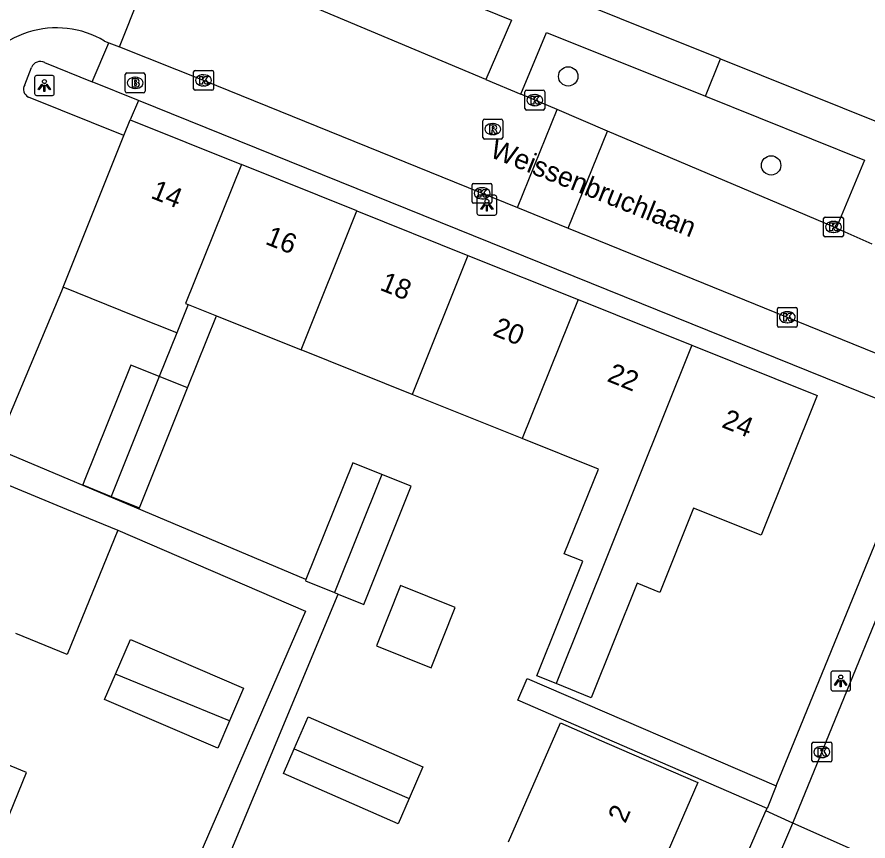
# Model space of a CAD drawing. Extents: x 162812 to 163818, y 381639 to 382470.
# Drawn here: x 163309.93 to 163352.9, y 382068.45 to 382110.03 of the extents above; entities that cross this region are included whole.
import ezdxf

# ---------------------------------------------------------------- set-up
doc = ezdxf.new("R2010")
doc.units = 0
for name, color, linetype in [('IMGEO_Boom', 7, 'Continuous'), ('IMGEO_Brandkraan', 7, 'Continuous'), ('IMGEO_Groenvoorziening', 7, 'Continuous'), ('IMGEO_Kolk', 7, 'Continuous'), ('IMGEO_Lichtpunt', 7, 'Continuous'), ('IMGEO_Openbare_ruimte_label', 7, 'Continuous'), ('IMGEO_Pand', 7, 'Continuous'), ('IMGEO_Pand_nummerreeks', 7, 'Continuous'), ('IMGEO_Parkeervlak_open', 7, 'Continuous'), ('IMGEO_Rijbaan_lokaal_open', 7, 'Continuous'), ('IMGEO_Rioolput', 7, 'Continuous'), ('IMGEO_Voetpad_open', 7, 'Continuous')]:
    doc.layers.add(name, color=color, linetype=linetype)

msp = doc.modelspace()

# ---------------------------------------------------------------- linework, layer by layer
at = {"layer": 'IMGEO_Boom'}
for centre in [(163337.76, 382107.037), (163348.006, 382102.545)]:
    msp.add_circle(centre, 0.489, dxfattribs=at)
at = {"layer": 'IMGEO_Brandkraan'}
for p, q in [((163315.397, 382106.284), (163315.397, 382107.136)), ((163315.472, 382107.21), (163316.324, 382107.21)), ((163316.398, 382107.136), (163316.398, 382106.284)), ((163315.885, 382106.99), (163315.91, 382106.99)), ((163315.908, 382106.43), (163315.883, 382106.43)), ((163316.324, 382106.21), (163315.472, 382106.21))]:
    msp.add_line(p, q, dxfattribs=at)
for points in [[(163315.397, 382106.284), (163315.397, 382107.136)], [(163315.472, 382107.21), (163316.324, 382107.21)], [(163316.398, 382107.136), (163316.398, 382106.284)], [(163315.745, 382106.91), (163315.745, 382106.51), (163315.958, 382106.51)], [(163315.976, 382106.91), (163315.745, 382106.91)], [(163315.924, 382106.829), (163315.87, 382106.829), (163315.87, 382106.753)], [(163315.87, 382106.753), (163315.923, 382106.753)], [(163315.932, 382106.677), (163315.87, 382106.677), (163315.87, 382106.596)], [(163315.87, 382106.596), (163315.932, 382106.596)], [(163316.324, 382106.21), (163315.472, 382106.21)]]:
    msp.add_lwpolyline(points, dxfattribs=at)
for centre, radius, start, end in [((163315.474, 382107.134), 0.0765, 91.552, 178.448), ((163315.474, 382107.134), 0.0765, 91.552, 178.448), ((163316.322, 382107.134), 0.0765, 1.552, 88.448), ((163316.322, 382107.134), 0.0765, 1.552, 88.448), ((163315.925, 382106.791), 0.0379, 267.8285, 90.9355), ((163315.933, 382106.636), 0.0404, 269.8759, 90.5077), ((163315.98, 382106.765), 0.145, 59.4692, 91.5367), ((163316.005, 382106.812), 0.0922, 285.5137, 58.1501), ((163316.01, 382106.62), 0.105, 301.3115, 78.989), ((163315.474, 382106.286), 0.0765, 181.552, 268.448), ((163315.474, 382106.286), 0.0765, 181.552, 268.448), ((163315.964, 382106.761), 0.251, 268.6676, 293.5347), ((163316.322, 382106.286), 0.0765, 271.552, 358.448), ((163316.322, 382106.286), 0.0765, 271.552, 358.448)]:
    msp.add_arc(centre, radius, start, end, dxfattribs=at)
for centre, major_axis, ratio, start_param, end_param in [((163315.884, 382106.71), (-0.387, 0.002), 0.722429, 4.712389, 7.853982), ((163315.909, 382106.71), (-0.39, 0.002), 0.717154, 1.570796, 4.712389)]:
    msp.add_ellipse(centre, major_axis=major_axis, ratio=ratio, start_param=start_param, end_param=end_param, dxfattribs=at)
at = {"layer": 'IMGEO_Groenvoorziening'}
msp.add_lwpolyline([(163316.062, 382105.827), (163315.649, 382104.847)], dxfattribs=at)
at = {"layer": 'IMGEO_Kolk'}
for p, q in [((163318.848, 382106.411), (163318.848, 382107.263)), ((163318.923, 382107.337), (163319.775, 382107.337)), ((163319.336, 382107.117), (163319.361, 382107.117)), ((163319.849, 382107.263), (163319.849, 382106.411)), ((163319.775, 382106.337), (163318.923, 382106.337)), ((163319.359, 382106.557), (163319.334, 382106.557)), ((163335.573, 382105.413), (163335.573, 382106.265)), ((163335.648, 382106.339), (163336.5, 382106.339)), ((163336.574, 382106.265), (163336.574, 382105.413)), ((163336.061, 382106.119), (163336.086, 382106.119)), ((163336.084, 382105.559), (163336.059, 382105.559)), ((163336.5, 382105.339), (163335.648, 382105.339)), ((163332.911, 382100.709), (163332.911, 382101.561)), ((163332.986, 382101.635), (163333.838, 382101.635)), ((163333.912, 382101.561), (163333.912, 382100.709)), ((163333.399, 382101.415), (163333.424, 382101.415)), ((163333.422, 382100.855), (163333.397, 382100.855)), ((163333.838, 382100.635), (163332.986, 382100.635)), ((163350.653, 382099.012), (163350.653, 382099.864)), ((163350.728, 382099.938), (163351.58, 382099.938)), ((163351.654, 382099.864), (163351.654, 382099.012)), ((163351.141, 382099.718), (163351.166, 382099.718)), ((163351.58, 382098.938), (163350.728, 382098.938)), ((163351.164, 382099.158), (163351.139, 382099.158)), ((163348.322, 382094.453), (163348.322, 382095.305)), ((163348.397, 382095.379), (163349.249, 382095.379)), ((163348.81, 382095.159), (163348.835, 382095.159)), ((163349.323, 382095.305), (163349.323, 382094.453)), ((163349.249, 382094.379), (163348.397, 382094.379)), ((163348.833, 382094.599), (163348.808, 382094.599)), ((163350.067, 382072.508), (163350.067, 382073.36)), ((163350.142, 382073.434), (163350.994, 382073.434)), ((163350.555, 382073.214), (163350.58, 382073.214)), ((163351.068, 382073.36), (163351.068, 382072.508)), ((163350.994, 382072.434), (163350.142, 382072.434)), ((163350.578, 382072.654), (163350.553, 382072.654))]:
    msp.add_line(p, q, dxfattribs=at)
for points in [[(163318.848, 382106.411), (163318.848, 382107.263)], [(163318.923, 382107.337), (163319.775, 382107.337)], [(163319.849, 382107.263), (163319.849, 382106.411)], [(163319.169, 382107.037), (163319.292, 382107.037), (163319.292, 382106.886), (163319.422, 382107.037), (163319.586, 382107.037), (163319.44, 382106.886), (163319.593, 382106.637), (163319.441, 382106.637), (163319.356, 382106.801), (163319.292, 382106.734), (163319.292, 382106.637), (163319.169, 382106.637), (163319.169, 382107.037)], [(163319.775, 382106.337), (163318.923, 382106.337)], [(163335.573, 382105.413), (163335.573, 382106.265)], [(163335.648, 382106.339), (163336.5, 382106.339)], [(163336.574, 382106.265), (163336.574, 382105.413)], [(163335.894, 382106.039), (163336.017, 382106.039), (163336.017, 382105.888), (163336.147, 382106.039), (163336.311, 382106.039), (163336.165, 382105.888), (163336.318, 382105.639), (163336.166, 382105.639), (163336.081, 382105.803), (163336.017, 382105.736), (163336.017, 382105.639), (163335.894, 382105.639), (163335.894, 382106.039)], [(163336.5, 382105.339), (163335.648, 382105.339)], [(163332.911, 382100.709), (163332.911, 382101.561)], [(163332.986, 382101.635), (163333.838, 382101.635)], [(163333.912, 382101.561), (163333.912, 382100.709)], [(163333.232, 382101.335), (163333.355, 382101.335), (163333.355, 382101.184), (163333.485, 382101.335), (163333.649, 382101.335), (163333.503, 382101.184), (163333.656, 382100.935), (163333.504, 382100.935), (163333.419, 382101.099), (163333.355, 382101.032), (163333.355, 382100.935), (163333.232, 382100.935), (163333.232, 382101.335)], [(163333.838, 382100.635), (163332.986, 382100.635)], [(163350.653, 382099.012), (163350.653, 382099.864)], [(163350.728, 382099.938), (163351.58, 382099.938)], [(163351.654, 382099.864), (163351.654, 382099.012)], [(163350.974, 382099.638), (163351.097, 382099.638), (163351.097, 382099.487), (163351.227, 382099.638), (163351.391, 382099.638), (163351.245, 382099.487), (163351.398, 382099.238), (163351.246, 382099.238), (163351.161, 382099.402), (163351.097, 382099.335), (163351.097, 382099.238), (163350.974, 382099.238), (163350.974, 382099.638)], [(163351.58, 382098.938), (163350.728, 382098.938)], [(163348.322, 382094.453), (163348.322, 382095.305)], [(163348.397, 382095.379), (163349.249, 382095.379)], [(163348.643, 382095.079), (163348.766, 382095.079), (163348.766, 382094.928), (163348.896, 382095.079), (163349.06, 382095.079), (163348.914, 382094.928), (163349.067, 382094.679), (163348.915, 382094.679), (163348.83, 382094.843), (163348.766, 382094.776), (163348.766, 382094.679), (163348.643, 382094.679), (163348.643, 382095.079)], [(163349.323, 382095.305), (163349.323, 382094.453)], [(163349.249, 382094.379), (163348.397, 382094.379)], [(163350.067, 382072.508), (163350.067, 382073.36)], [(163350.142, 382073.434), (163350.994, 382073.434)], [(163351.068, 382073.36), (163351.068, 382072.508)], [(163350.388, 382073.134), (163350.511, 382073.134), (163350.511, 382072.983), (163350.641, 382073.134), (163350.805, 382073.134), (163350.659, 382072.983), (163350.812, 382072.734), (163350.66, 382072.734), (163350.575, 382072.898), (163350.511, 382072.831), (163350.511, 382072.734), (163350.388, 382072.734), (163350.388, 382073.134)], [(163350.994, 382072.434), (163350.142, 382072.434)]]:
    msp.add_lwpolyline(points, dxfattribs=at)
for centre, start, end in [((163318.925, 382107.261), 91.552, 178.448), ((163318.925, 382107.261), 91.552, 178.448), ((163319.773, 382107.261), 1.552, 88.448), ((163319.773, 382107.261), 1.552, 88.448), ((163318.925, 382106.413), 181.552, 268.448), ((163318.925, 382106.413), 181.552, 268.448), ((163319.773, 382106.413), 271.552, 358.448), ((163319.773, 382106.413), 271.552, 358.448), ((163335.65, 382106.263), 91.552, 178.448), ((163335.65, 382106.263), 91.552, 178.448), ((163336.498, 382106.263), 1.552, 88.448), ((163336.498, 382106.263), 1.552, 88.448), ((163335.65, 382105.415), 181.552, 268.448), ((163335.65, 382105.415), 181.552, 268.448), ((163336.498, 382105.415), 271.552, 358.448), ((163336.498, 382105.415), 271.552, 358.448), ((163332.988, 382101.559), 91.552, 178.448), ((163332.988, 382101.559), 91.552, 178.448), ((163333.836, 382101.559), 1.552, 88.448), ((163333.836, 382101.559), 1.552, 88.448), ((163332.988, 382100.711), 181.552, 268.448), ((163332.988, 382100.711), 181.552, 268.448), ((163333.836, 382100.711), 271.552, 358.448), ((163333.836, 382100.711), 271.552, 358.448), ((163350.73, 382099.862), 91.552, 178.448), ((163350.73, 382099.862), 91.552, 178.448), ((163351.578, 382099.862), 1.552, 88.448), ((163351.578, 382099.862), 1.552, 88.448), ((163350.73, 382099.014), 181.552, 268.448), ((163350.73, 382099.014), 181.552, 268.448), ((163351.578, 382099.014), 271.552, 358.448), ((163351.578, 382099.014), 271.552, 358.448), ((163348.399, 382095.303), 91.552, 178.448), ((163348.399, 382095.303), 91.552, 178.448), ((163349.247, 382095.303), 1.552, 88.448), ((163349.247, 382095.303), 1.552, 88.448), ((163348.399, 382094.455), 181.552, 268.448), ((163348.399, 382094.455), 181.552, 268.448), ((163349.247, 382094.455), 271.552, 358.448), ((163349.247, 382094.455), 271.552, 358.448), ((163350.144, 382073.358), 91.552, 178.448), ((163350.144, 382073.358), 91.552, 178.448), ((163350.992, 382073.358), 1.552, 88.448), ((163350.992, 382073.358), 1.552, 88.448), ((163350.144, 382072.51), 181.552, 268.448), ((163350.144, 382072.51), 181.552, 268.448), ((163350.992, 382072.51), 271.552, 358.448), ((163350.992, 382072.51), 271.552, 358.448)]:
    msp.add_arc(centre, 0.0765, start, end, dxfattribs=at)
for centre, major_axis, ratio, start_param, end_param in [((163319.335, 382106.837), (-0.387, 0.002), 0.722429, 4.712389, 7.853982), ((163319.36, 382106.837), (-0.39, 0.002), 0.717154, 1.570796, 4.712389), ((163336.06, 382105.839), (-0.387, 0.002), 0.722429, 4.712389, 7.853982), ((163336.085, 382105.839), (-0.39, 0.002), 0.717154, 1.570796, 4.712389), ((163333.398, 382101.135), (-0.387, 0.002), 0.722429, 4.712389, 7.853982), ((163333.423, 382101.135), (-0.39, 0.002), 0.717154, 1.570796, 4.712389), ((163351.14, 382099.438), (-0.387, 0.002), 0.722429, 4.712389, 7.853982), ((163351.165, 382099.438), (-0.39, 0.002), 0.717154, 1.570796, 4.712389), ((163348.809, 382094.879), (-0.387, 0.002), 0.722429, 4.712389, 7.853982), ((163348.834, 382094.879), (-0.39, 0.002), 0.717154, 1.570796, 4.712389), ((163350.554, 382072.934), (-0.387, 0.002), 0.722429, 4.712389, 7.853982), ((163350.579, 382072.934), (-0.39, 0.002), 0.717154, 1.570796, 4.712389)]:
    msp.add_ellipse(centre, major_axis=major_axis, ratio=ratio, start_param=start_param, end_param=end_param, dxfattribs=at)
at = {"layer": 'IMGEO_Lichtpunt'}
for p, q in [((163310.816, 382106.98), (163310.816, 382106.173)), ((163310.816, 382106.98), (163310.816, 382106.173)), ((163311.718, 382107.075), (163310.91, 382107.075)), ((163311.718, 382107.075), (163310.91, 382107.075)), ((163311.812, 382106.173), (163311.812, 382106.98)), ((163311.812, 382106.173), (163311.812, 382106.98)), ((163310.91, 382106.079), (163311.718, 382106.079)), ((163310.91, 382106.079), (163311.718, 382106.079)), ((163333.154, 382100.941), (163333.154, 382100.134)), ((163333.154, 382100.941), (163333.154, 382100.134)), ((163334.056, 382101.036), (163333.248, 382101.036)), ((163334.056, 382101.036), (163333.248, 382101.036)), ((163334.15, 382100.134), (163334.15, 382100.941)), ((163334.15, 382100.134), (163334.15, 382100.941)), ((163333.248, 382100.04), (163334.056, 382100.04)), ((163333.248, 382100.04), (163334.056, 382100.04)), ((163351.924, 382077.019), (163351.116, 382077.019)), ((163351.924, 382077.019), (163351.116, 382077.019)), ((163351.022, 382076.924), (163351.022, 382076.117)), ((163351.022, 382076.924), (163351.022, 382076.117)), ((163352.018, 382076.117), (163352.018, 382076.924)), ((163352.018, 382076.117), (163352.018, 382076.924)), ((163351.116, 382076.023), (163351.924, 382076.023)), ((163351.116, 382076.023), (163351.924, 382076.023))]:
    msp.add_line(p, q, dxfattribs=at)
for points in [[(163311.19, 382106.644), (163311.229, 382106.616), (163311.041, 382106.354), (163311.003, 382106.381), (163311.19, 382106.644)], [(163311.292, 382106.596), (163311.339, 382106.596), (163311.339, 382106.274), (163311.292, 382106.274), (163311.292, 382106.596)], [(163311.402, 382106.616), (163311.44, 382106.643), (163311.627, 382106.381), (163311.588, 382106.353), (163311.402, 382106.616)], [(163333.528, 382100.605), (163333.567, 382100.577), (163333.379, 382100.315), (163333.341, 382100.342), (163333.528, 382100.605)], [(163333.63, 382100.557), (163333.677, 382100.557), (163333.677, 382100.235), (163333.63, 382100.235), (163333.63, 382100.557)], [(163333.74, 382100.577), (163333.778, 382100.604), (163333.965, 382100.342), (163333.926, 382100.314), (163333.74, 382100.577)], [(163351.396, 382076.588), (163351.435, 382076.56), (163351.247, 382076.298), (163351.209, 382076.325), (163351.396, 382076.588)], [(163351.608, 382076.56), (163351.646, 382076.587), (163351.833, 382076.325), (163351.794, 382076.297), (163351.608, 382076.56)], [(163351.498, 382076.54), (163351.545, 382076.54), (163351.545, 382076.218), (163351.498, 382076.218), (163351.498, 382076.54)]]:
    msp.add_lwpolyline(points, dxfattribs=at)
for centre in [(163311.315, 382106.778), (163333.653, 382100.739), (163351.521, 382076.722)]:
    msp.add_circle(centre, 0.0994, dxfattribs=at)
for centre, start, end in [((163310.91, 382106.98), 90, 180), ((163310.91, 382106.98), 90, 180), ((163311.718, 382106.98), 0, 90), ((163311.718, 382106.98), 0, 90), ((163310.91, 382106.173), 180, 270), ((163310.91, 382106.173), 180, 270), ((163311.718, 382106.173), 270, 0), ((163311.718, 382106.173), 270, 360), ((163333.248, 382100.941), 90, 180), ((163333.248, 382100.941), 90, 180), ((163334.056, 382100.941), 0, 90), ((163334.056, 382100.941), 0, 90), ((163333.248, 382100.134), 180, 270), ((163333.248, 382100.134), 180, 270), ((163334.056, 382100.134), 270, 0), ((163334.056, 382100.134), 270, 360), ((163351.116, 382076.924), 90, 180), ((163351.116, 382076.924), 90, 180), ((163351.924, 382076.924), 0, 90), ((163351.924, 382076.924), 0, 90), ((163351.116, 382076.117), 180, 270), ((163351.116, 382076.117), 180, 270), ((163351.924, 382076.117), 270, 0), ((163351.924, 382076.117), 270, 360)]:
    msp.add_arc(centre, 0.0946, start, end, dxfattribs=at)
at = {"layer": 'IMGEO_Pand'}
for points in [[(163315.33, 382104.052), (163315.649, 382104.847)], [(163315.649, 382104.847), (163321.261, 382102.595)], [(163312.257, 382096.396), (163315.33, 382104.052)], [(163321.261, 382102.595), (163318.444, 382095.575), (163318.571, 382095.524)], [(163327.09, 382100.255), (163321.261, 382102.595)], [(163324.273, 382093.236), (163327.09, 382100.255)], [(163327.09, 382100.255), (163332.699, 382098.004)], [(163332.699, 382098.004), (163329.882, 382090.985)], [(163332.699, 382098.004), (163338.26, 382095.772)], [(163317.997, 382094.093), (163315.88, 382094.942), (163312.257, 382096.396)], [(163318.571, 382095.524), (163317.997, 382094.093)], [(163318.571, 382095.524), (163320.005, 382094.949)], [(163338.26, 382095.772), (163335.443, 382088.753)], [(163338.26, 382095.772), (163343.998, 382093.469)], [(163318.546, 382091.314), (163320.005, 382094.949)], [(163320.005, 382094.949), (163324.273, 382093.236)], [(163317.997, 382094.093), (163317.112, 382091.889)], [(163343.998, 382093.469), (163350.337, 382090.925), (163347.506, 382083.873), (163344.092, 382085.245), (163342.385, 382080.995), (163341.244, 382081.454), (163338.924, 382075.674), (163337.144, 382076.388)], [(163343.998, 382093.469), (163337.144, 382076.388)], [(163329.882, 382090.985), (163324.273, 382093.236)], [(163317.112, 382091.889), (163316.985, 382091.94), (163315.678, 382092.464), (163313.329, 382086.613), (163313.25, 382086.415), (163314.683, 382085.839)], [(163317.112, 382091.889), (163314.683, 382085.839)], [(163318.546, 382091.314), (163318.333, 382091.399), (163317.112, 382091.889)], [(163314.683, 382085.839), (163316.117, 382085.264), (163318.546, 382091.314)], [(163335.443, 382088.753), (163329.882, 382090.985)], [(163337.144, 382076.388), (163336.173, 382076.778), (163338.493, 382082.561), (163337.564, 382082.934), (163339.283, 382087.212), (163335.443, 382088.753)], [(163328.356, 382086.94), (163326.884, 382087.531), (163324.52, 382081.642)], [(163308.265, 382086.902), (163309.954, 382086.213), (163312.438, 382085.197), (163315.027, 382084.14)], [(163328.356, 382086.94), (163325.963, 382080.979)], [(163326.145, 382080.906), (163327.435, 382080.388), (163329.828, 382086.349), (163328.356, 382086.94)], [(163315.027, 382084.14), (163312.464, 382077.865), (163309.875, 382078.922)], [(163324.52, 382081.642), (163324.491, 382081.57), (163325.963, 382080.979)], [(163328.079, 382078.291), (163330.834, 382077.186), (163332.054, 382080.227), (163329.3, 382081.333), (163328.079, 382078.291)], [(163325.963, 382080.979), (163326.145, 382080.906)], [(163314.902, 382076.869), (163315.654, 382078.616), (163321.367, 382076.157), (163320.661, 382074.517)], [(163320.661, 382074.517), (163320.064, 382073.13), (163314.351, 382075.589), (163314.902, 382076.869)], [(163320.661, 382074.517), (163314.902, 382076.869)], [(163323.931, 382073.101), (163324.639, 382074.719), (163330.427, 382072.184), (163329.726, 382070.583)], [(163334.751, 382068.399), (163337.363, 382074.41), (163339.718, 382073.388), (163344.303, 382071.395), (163341.691, 382065.383)], [(163305.176, 382067.417), (163308.095, 382066.225), (163310.414, 382071.903), (163307.495, 382073.095)], [(163329.726, 382070.583), (163329.172, 382069.317), (163323.384, 382071.852), (163323.931, 382073.101)], [(163323.931, 382073.101), (163329.726, 382070.583)]]:
    msp.add_lwpolyline(points, dxfattribs=at)
at = {"layer": 'IMGEO_Parkeervlak_open'}
for points in [[(163311.327, 382107.731), (163313.728, 382106.765)], [(163310.318, 382106.618), (163310.66, 382107.494)], [(163315.33, 382104.052), (163310.51, 382105.986)], [(163312.257, 382096.396), (163309.494, 382089.826)]]:
    msp.add_lwpolyline(points, dxfattribs=at)
for centre, radius, start, end in [((163311.104, 382107.303), 0.483, 62.4379, 156.6847), ((163310.726, 382106.397), 0.464, 151.5647, 242.2326)]:
    msp.add_arc(centre, radius, start, end, dxfattribs=at)
at = {"layer": 'IMGEO_Rijbaan_lokaal_open'}
for points in [[(163315.105, 382108.523), (163317.167, 382113.689)], [(163333.609, 382106.878), (163321.539, 382111.966), (163318.948, 382112.982)], [(163314.353, 382108.821), (163314.573, 382108.734)], [(163314.573, 382108.734), (163315.105, 382108.523)], [(163315.105, 382108.523), (163319.378, 382106.827), (163335.196, 382100.412)], [(163333.609, 382106.878), (163335.371, 382106.135)], [(163337.2, 382105.36), (163335.371, 382106.135)], [(163335.196, 382100.412), (163337.2, 382105.36)], [(163339.744, 382104.28), (163337.2, 382105.36)], [(163337.756, 382099.373), (163339.744, 382104.28)], [(163351.288, 382099.377), (163351.153, 382099.437), (163339.744, 382104.28)], [(163335.196, 382100.412), (163337.756, 382099.373)], [(163337.756, 382099.373), (163348.731, 382094.918), (163353.295, 382093.06)], [(163353.105, 382098.563), (163351.288, 382099.377)], [(163349.1, 382069.351), (163356.292, 382086.917)], [(163334.915, 382036.546), (163340.935, 382050.494), (163346.757, 382063.88), (163349.1, 382069.351)], [(163352.519, 382067.829), (163349.1, 382069.351)]]:
    msp.add_lwpolyline(points, dxfattribs=at)
msp.add_arc((163311.926, 382104.728), 4.758, 59.3308, 155.7049, dxfattribs=at)
at = {"layer": 'IMGEO_Rioolput'}
for p, q in [((163333.455, 382103.95), (163333.455, 382104.802)), ((163333.53, 382104.876), (163334.382, 382104.876)), ((163333.943, 382104.656), (163333.968, 382104.656)), ((163334.456, 382104.802), (163334.456, 382103.95)), ((163333.966, 382104.096), (163333.941, 382104.096)), ((163334.382, 382103.876), (163333.53, 382103.876))]:
    msp.add_line(p, q, dxfattribs=at)
for points in [[(163333.455, 382103.95), (163333.455, 382104.802)], [(163333.53, 382104.876), (163334.382, 382104.876)], [(163334.044, 382104.574), (163333.792, 382104.576), (163333.792, 382104.176)], [(163334.456, 382104.802), (163334.456, 382103.95)], [(163333.792, 382104.176), (163333.916, 382104.176), (163333.916, 382104.338), (163333.927, 382104.338)], [(163333.97, 382104.495), (163333.916, 382104.495), (163333.916, 382104.414)], [(163333.916, 382104.414), (163333.968, 382104.414)], [(163333.974, 382104.309), (163334.045, 382104.176), (163334.185, 382104.176), (163334.12, 382104.302)], [(163334.382, 382103.876), (163333.53, 382103.876)]]:
    msp.add_lwpolyline(points, dxfattribs=at)
for centre, radius, start, end in [((163333.532, 382104.8), 0.0765, 91.552, 178.448), ((163333.532, 382104.8), 0.0765, 91.552, 178.448), ((163334.043, 382104.464), 0.109, 350.3612, 89.416), ((163334.38, 382104.8), 0.0765, 1.552, 88.448), ((163334.38, 382104.8), 0.0765, 1.552, 88.448), ((163333.926, 382104.285), 0.0533, 26.0293, 88.6989), ((163333.952, 382104.603), 0.19, 274.7715, 282.9687), ((163333.976, 382104.399), 0.0964, 77.0061, 93.1865), ((163333.99, 382104.456), 0.0378, 276.6634, 79.6772), ((163334.041, 382104.464), 0.112, 277.5842, 350.9817), ((163334.025, 382104.249), 0.108, 29.5134, 73.7905), ((163333.532, 382103.952), 0.0765, 181.552, 268.448), ((163333.532, 382103.952), 0.0765, 181.552, 268.448), ((163334.38, 382103.952), 0.0765, 271.552, 358.448), ((163334.38, 382103.952), 0.0765, 271.552, 358.448)]:
    msp.add_arc(centre, radius, start, end, dxfattribs=at)
for centre, major_axis, ratio, start_param, end_param in [((163333.942, 382104.376), (-0.387, 0.002), 0.722429, 4.712389, 7.853982), ((163333.967, 382104.376), (-0.39, 0.002), 0.717154, 1.570796, 4.712389)]:
    msp.add_ellipse(centre, major_axis=major_axis, ratio=ratio, start_param=start_param, end_param=end_param, dxfattribs=at)
at = {"layer": 'IMGEO_Voetpad_open'}
for points in [[(163318.948, 382112.982), (163320.087, 382115.873), (163334.894, 382109.877), (163333.609, 382106.878)], [(163345.456, 382107.927), (163330.2, 382114.053)], [(163335.371, 382106.135), (163336.67, 382109.257), (163344.697, 382106.036)], [(163313.728, 382106.765), (163314.573, 382108.734)], [(163344.697, 382106.036), (163345.456, 382107.927)], [(163345.456, 382107.927), (163361.874, 382101.334), (163416.208, 382079.515)], [(163316.062, 382105.827), (163313.728, 382106.765)], [(163353.303, 382090.772), (163316.062, 382105.827)], [(163344.697, 382106.036), (163352.724, 382102.815), (163351.288, 382099.377)], [(163348.267, 382071.233), (163355.096, 382087.936), (163354.127, 382090.439), (163353.303, 382090.772)], [(163324.52, 382081.642), (163308.836, 382088.261)], [(163315.027, 382084.14), (163324.491, 382080.044), (163314.095, 382056.11), (163315.541, 382055.478), (163326.145, 382080.906)], [(163347.8, 382070.092), (163335.218, 382075.552), (163335.688, 382076.642), (163348.267, 382071.233)], [(163348.267, 382071.233), (163347.8, 382070.092)], [(163320.918, 382012.914), (163322.712, 382012.16), (163347.746, 382069.96)], [(163347.746, 382069.96), (163347.8, 382070.092)], [(163349.1, 382069.351), (163347.746, 382069.96)]]:
    msp.add_lwpolyline(points, dxfattribs=at)

# ---------------------------------------------------------------- texts
at = {"layer": 'IMGEO_Openbare_ruimte_label'}
msp.add_text('Weissenbruchlaan', height=1, rotation=338.156, dxfattribs=at).set_placement((163333.746, 382102.991))
at = {"layer": 'IMGEO_Pand_nummerreeks'}
for s, rotation, p in [('14', 338.1302, (163316.635, 382100.917)), ('16', 338.1302, (163322.416, 382098.596)), ('18', 338.132, (163328.201, 382096.275)), ('20', 338.132, (163333.899, 382093.989)), ('22', 338.132, (163339.674, 382091.67)), ('24', 338.132, (163345.458, 382089.349)), ('2', 66.5184, (163340.643, 382069.295))]:
    msp.add_text(s, height=1, rotation=rotation, dxfattribs=at).set_placement(p)

doc.saveas('drawing.dxf')
